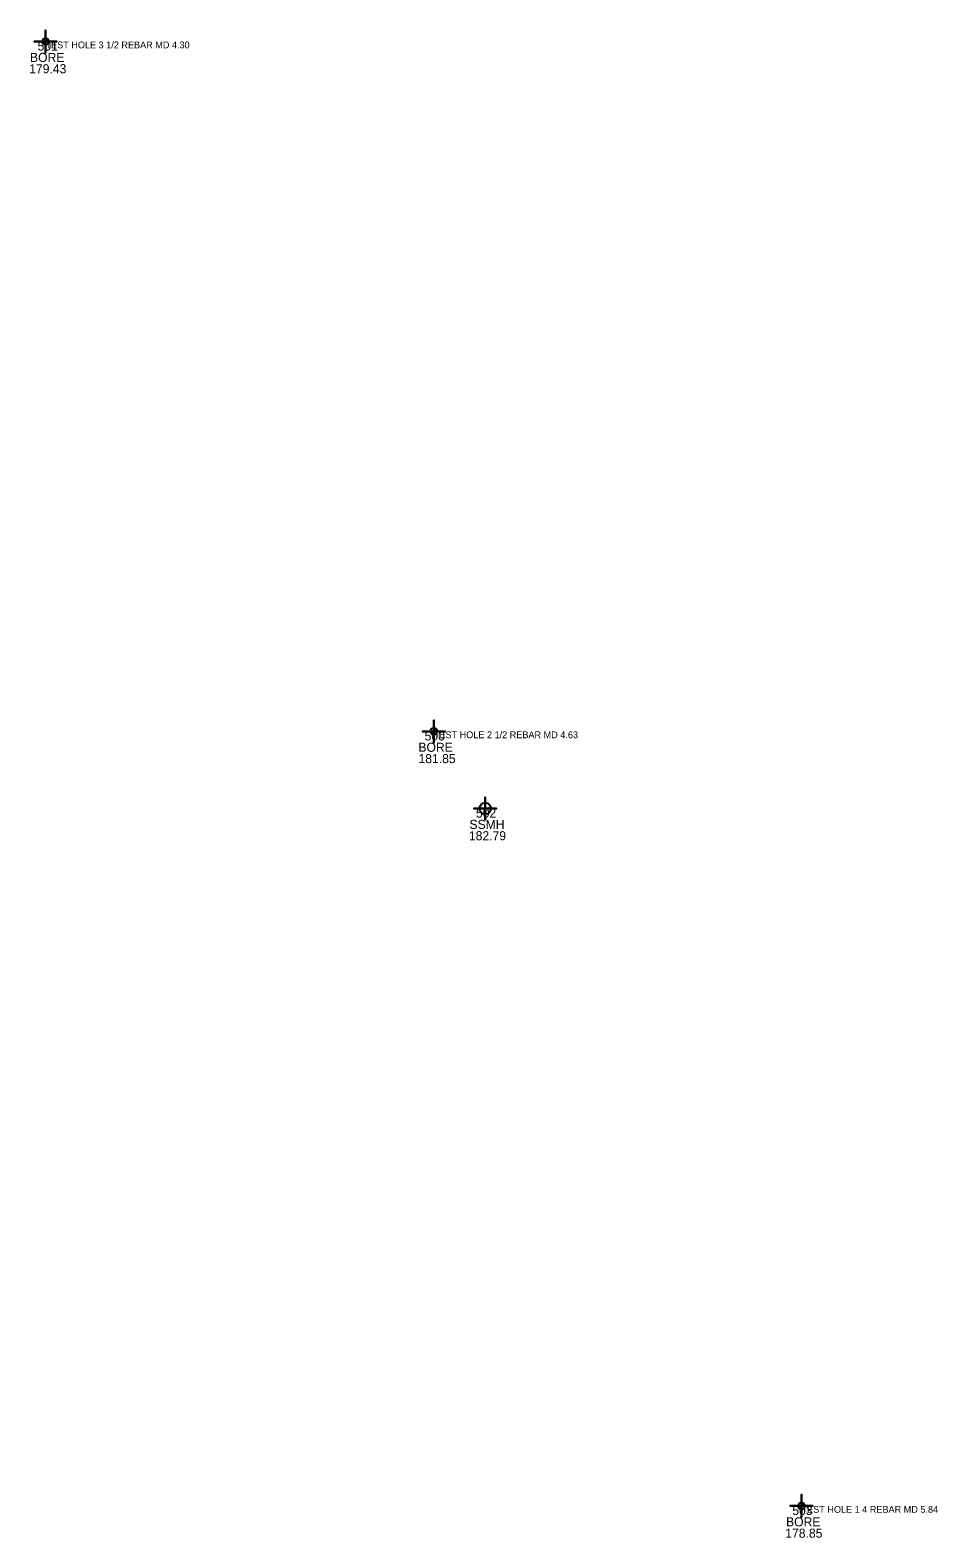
# Model space of a CAD drawing. Extents: x 1969314 to 1970910, y 795817 to 797766.
# Drawn here: x 1970709.8 to 1970909.8, y 795816.6 to 796148.9 of the extents above; entities that cross this region are included whole.
import ezdxf

# ---------------------------------------------------------------- set-up
doc = ezdxf.new("R2010")
doc.units = 0
for name, color, linetype in [('Level 63', 7, 'Continuous'), ('SV_Control_Boring', 7, 'Continuous'), ('SV_Control_Boring_Code', 7, 'Continuous'), ('SV_Control_Boring_Elev', 7, 'Continuous'), ('SV_Control_Boring_Name', 7, 'Continuous'), ('SV_Control_Boring_Shot', 7, 'Continuous'), ('SV_SS_Appurt_Code', 7, 'Continuous'), ('SV_SS_Appurt_Elev', 7, 'Continuous'), ('SV_SS_Appurt_name', 7, 'Continuous'), ('SV_SS_Appurtenances', 7, 'Continuous'), ('SV_SS_Appurtenances_Shots', 7, 'Continuous')]:
    doc.layers.add(name, color=color, linetype=linetype)

msp = doc.modelspace()

# ---------------------------------------------------------------- linework, layer by layer
at = {"layer": 'SV_Control_Boring'}
for p, q in [((1970712.4, 796146.35), (1970713.9, 796146.35)), ((1970713.15, 796145.6), (1970713.15, 796147.1)), ((1970798.73, 795993.55), (1970798.73, 795995.05)), ((1970797.98, 795994.3), (1970799.48, 795994.3)), ((1970879, 795823.58), (1970880.5, 795823.58)), ((1970879.75, 795822.83), (1970879.75, 795824.33))]:
    msp.add_line(p, q, dxfattribs=at)
for centre in [(1970713.15, 796146.35), (1970798.73, 795994.3), (1970879.75, 795823.58)]:
    msp.add_circle(centre, 0.75, dxfattribs=at)
for centre, radius, start, end in [((1970713.15, 796146.35), 0.698, 179.9999, 270.0002), ((1970713.15, 796146.35), 0.635, 179.9999, 270.0002), ((1970713.15, 796146.35), 0.573, 179.9999, 270.0002), ((1970713.15, 796146.35), 0.51, 179.9999, 270.0002), ((1970713.15, 796146.35), 0.448, 179.9999, 270.0002), ((1970713.15, 796146.35), 0.385, 179.9999, 270.0002), ((1970713.15, 796146.35), 0.693, 0.0001, 89.9995), ((1970713.15, 796146.35), 0.631, 0.0001, 89.9995), ((1970713.15, 796146.35), 0.569, 0.0001, 89.9995), ((1970713.15, 796146.35), 0.507, 0.0001, 89.9995), ((1970713.15, 796146.35), 0.445, 0.0001, 89.9995), ((1970713.15, 796146.35), 0.384, 0.0001, 89.9995), ((1970713.15, 796146.35), 0.322, 0.0001, 89.9995), ((1970798.73, 795994.3), 0.693, 0.0001, 89.9995), ((1970798.73, 795994.3), 0.631, 0.0001, 89.9995), ((1970798.73, 795994.3), 0.569, 0.0001, 89.9995), ((1970798.73, 795994.3), 0.507, 0.0001, 89.9995), ((1970798.73, 795994.3), 0.445, 0.0001, 89.9995), ((1970798.73, 795994.3), 0.698, 179.9999, 270.0002), ((1970798.73, 795994.3), 0.635, 179.9999, 270.0002), ((1970798.73, 795994.3), 0.573, 179.9999, 270.0002), ((1970798.73, 795994.3), 0.51, 179.9999, 270.0002), ((1970798.73, 795994.3), 0.448, 179.9999, 270.0002), ((1970798.73, 795994.3), 0.385, 179.9999, 270.0002), ((1970798.73, 795994.3), 0.384, 0.0001, 89.9995), ((1970798.73, 795994.3), 0.322, 0.0001, 89.9995), ((1970879.75, 795823.58), 0.698, 179.9999, 270.0002), ((1970879.75, 795823.58), 0.635, 179.9999, 270.0002), ((1970879.75, 795823.58), 0.573, 179.9999, 270.0002), ((1970879.75, 795823.58), 0.51, 179.9999, 270.0002), ((1970879.75, 795823.58), 0.448, 179.9999, 270.0002), ((1970879.75, 795823.58), 0.385, 179.9999, 270.0002), ((1970879.75, 795823.58), 0.693, 0.0001, 89.9995), ((1970879.75, 795823.58), 0.631, 0.0001, 89.9995), ((1970879.75, 795823.58), 0.569, 0.0001, 89.9995), ((1970879.75, 795823.58), 0.507, 0.0001, 89.9995), ((1970879.75, 795823.58), 0.445, 0.0001, 89.9995), ((1970879.75, 795823.58), 0.384, 0.0001, 89.9995), ((1970879.75, 795823.58), 0.322, 0.0001, 89.9995)]:
    msp.add_arc(centre, radius, start, end, dxfattribs=at)
at = {"layer": 'SV_Control_Boring_Shot'}
for points in [[(1970713.15, 796146.35), (1970713.15, 796148.85), (1970713.15, 796146.35), (1970710.65, 796146.35), (1970713.15, 796146.35), (1970713.15, 796143.85), (1970713.15, 796146.35), (1970715.65, 796146.35)], [(1970798.73, 795994.3), (1970798.73, 795996.8), (1970798.73, 795994.3), (1970796.23, 795994.3), (1970798.73, 795994.3), (1970798.73, 795991.8), (1970798.73, 795994.3), (1970801.23, 795994.3)], [(1970879.75, 795823.58), (1970879.75, 795826.08), (1970879.75, 795823.58), (1970877.25, 795823.58), (1970879.75, 795823.58), (1970879.75, 795821.08), (1970879.75, 795823.58), (1970882.25, 795823.58)]]:
    msp.add_lwpolyline(points, close=True, dxfattribs=at)
at = {"layer": 'SV_SS_Appurtenances'}
msp.add_circle((1970810.04, 795977.3), 1.25, dxfattribs=at)
at = {"layer": 'SV_SS_Appurtenances_Shots'}
msp.add_lwpolyline([(1970810.04, 795977.3), (1970810.04, 795979.8), (1970810.04, 795977.3), (1970807.54, 795977.3), (1970810.04, 795977.3), (1970810.04, 795974.8), (1970810.04, 795977.3), (1970812.54, 795977.3)], close=True, dxfattribs=at)

# ---------------------------------------------------------------- texts
at = {"layer": 'Level 63'}
for s, p in [('TEST HOLE 3 1/2 REBAR MD 4.30', (1970713.15, 796144.85)), ('TEST HOLE 2 1/2 REBAR MD 4.63', (1970798.73, 795992.8)), ('TEST HOLE 1 4 REBAR MD 5.84', (1970879.75, 795822.08))]:
    msp.add_text(s, height=1.5, dxfattribs=at).set_placement(p)
at = {"layer": 'SV_Control_Boring_Code'}
for p in [(1970709.73, 796141.85), (1970795.32, 795989.8), (1970876.34, 795819.08)]:
    msp.add_text('BORE', height=2, dxfattribs=at).set_placement(p)
at = {"layer": 'SV_Control_Boring_Elev'}
for s, p in [('179.43', (1970709.56, 796139.35)), ('181.85', (1970795.34, 795987.3)), ('178.85', (1970876.17, 795816.58))]:
    msp.add_text(s, height=2, dxfattribs=at).set_placement(p)
at = {"layer": 'SV_Control_Boring_Name'}
for s, p in [('501', (1970711.41, 796144.35)), ('500', (1970796.69, 795992.3)), ('503', (1970877.72, 795821.58))]:
    msp.add_text(s, height=2, dxfattribs=at).set_placement(p)
at = {"layer": 'SV_SS_Appurt_Code'}
msp.add_text('SSMH', height=2, dxfattribs=at).set_placement((1970806.57, 795972.8))
at = {"layer": 'SV_SS_Appurt_Elev'}
msp.add_text('182.79', height=2, dxfattribs=at).set_placement((1970806.46, 795970.3))
at = {"layer": 'SV_SS_Appurt_name'}
msp.add_text('502', height=2, dxfattribs=at).set_placement((1970808.01, 795975.3))
at = {"layer": 'SV_SS_Appurtenances'}
for s, rotation, p in [('N', 17.6281, (1970809.75, 795977.94)), ('H', 358.9101, (1970810.01, 795977.99)), ('M', 64.4229, (1970809.36, 795977.5)), ('C', 319.2946, (1970809.36, 795976.7)), ('A', 36.346, (1970809.52, 795977.78)), ('O', 338.0125, (1970809.62, 795976.5)), ('V', 6.0894, (1970810.01, 795976.39)), ('E', 24.8073, (1970810.34, 795976.44)), ('O', 330.8333, (1970810.28, 795977.96)), ('R', 43.5252, (1970810.61, 795976.6)), ('L', 312.1153, (1970810.52, 795977.81)), ('E', 293.3974, (1970810.66, 795977.61))]:
    msp.add_text(s, height=0.2, rotation=rotation, dxfattribs=at).set_placement(p)

doc.saveas('drawing.dxf')
